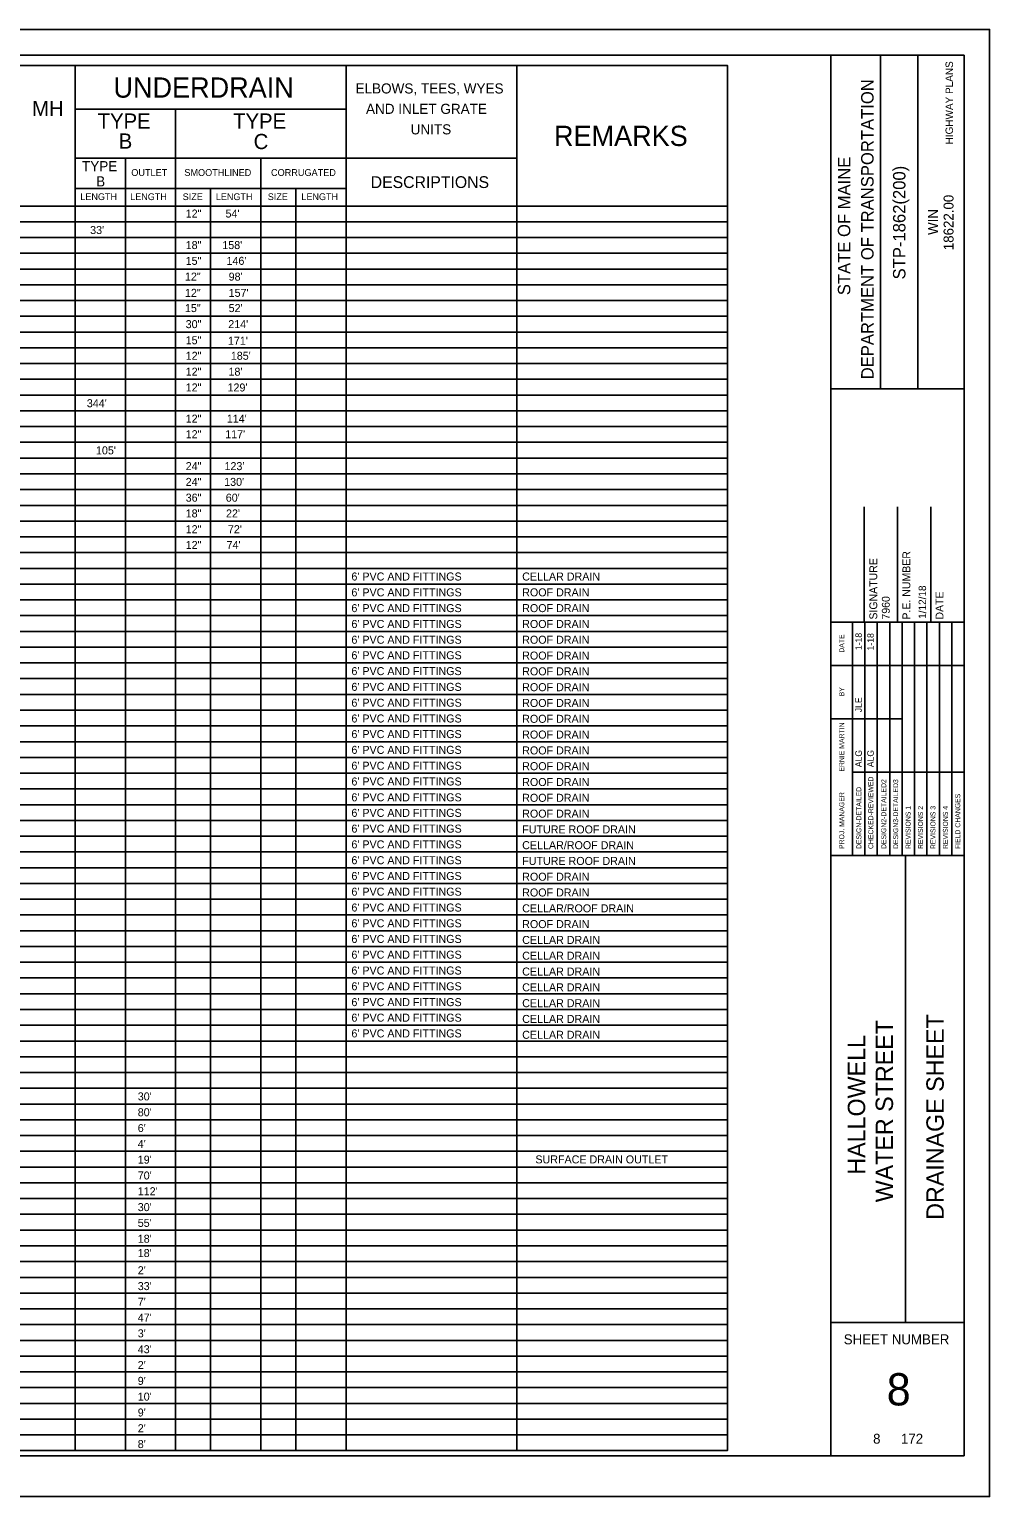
# Model space of a CAD drawing. Extents: x -0.13 to 2.7, y -0.05 to 1.78.
# Drawn here: x 1.498 to 2.698, y -0.051 to 1.782 of the extents above; entities that cross this region are included whole.
import ezdxf

# ---------------------------------------------------------------- set-up
doc = ezdxf.new("R2010")
doc.units = 0
for name, color, linetype in [('ANNOTATION', 7, 'Continuous'), ('BORDER', 7, 'Continuous'), ('PLOT BOUNDARY', 7, 'Continuous')]:
    doc.layers.add(name, color=color, linetype=linetype)

msp = doc.modelspace()

# ---------------------------------------------------------------- linework, layer by layer
at = {"layer": 'BORDER'}
for p, q in [((2.6667, 1.75), (0, 1.75)), ((2.5, 0), (2.5, 1.75)), ((2.5621, 1.3333), (2.5621, 1.75)), ((2.6087, 1.3333), (2.6087, 1.75)), ((2.6667, 0), (2.6667, 1.75)), ((1.5556, 1.6825), (1.5556, 1.7373)), ((1.8942, 1.6825), (1.8942, 1.7373)), ((2.1075, 1.6825), (2.1075, 1.7373)), ((1.5556, 1.6214), (1.5556, 1.6825)), ((1.5556, 1.6825), (1.6184, 1.6825)), ((1.6184, 1.6825), (1.7249, 1.6825)), ((1.6811, 1.6214), (1.6811, 1.6825)), ((1.7249, 1.6825), (1.7876, 1.6825)), ((1.7876, 1.6825), (1.8315, 1.6825)), ((1.8315, 1.6825), (1.8942, 1.6825)), ((1.8942, 1.6214), (1.8942, 1.6825)), ((2.1075, 1.6214), (2.1075, 1.6825)), ((1.5556, 1.5836), (1.5556, 1.6214)), ((1.5556, 1.6214), (1.6184, 1.6214)), ((1.6184, 1.5836), (1.6184, 1.6214)), ((1.6184, 1.6214), (1.7249, 1.6214)), ((1.6811, 1.5836), (1.6811, 1.6214)), ((1.7249, 1.6214), (1.8315, 1.6214)), ((1.7876, 1.5836), (1.7876, 1.6214)), ((1.8315, 1.6214), (1.8942, 1.6214)), ((1.8942, 1.5836), (1.8942, 1.6214)), ((1.8942, 1.6214), (2.1075, 1.6214)), ((2.1075, 1.5836), (2.1075, 1.6214)), ((1.5556, 1.5616), (1.5556, 1.5836)), ((1.5556, 1.5836), (1.6184, 1.5836)), ((1.6184, 1.5616), (1.6184, 1.5836)), ((1.6184, 1.5836), (1.6811, 1.5836)), ((1.6811, 1.5616), (1.6811, 1.5836)), ((1.6811, 1.5836), (1.7249, 1.5836)), ((1.7249, 1.5616), (1.7249, 1.5836)), ((1.7249, 1.5836), (1.7876, 1.5836)), ((1.7876, 1.5616), (1.7876, 1.5836)), ((1.7876, 1.5836), (1.8315, 1.5836)), ((1.8315, 1.5616), (1.8315, 1.5836)), ((1.8315, 1.5836), (1.8942, 1.5836)), ((1.8942, 1.5616), (1.8942, 1.5836)), ((2.1075, 1.5616), (2.1075, 1.5836)), ((1.5556, 1.5616), (1.5556, 0.0065)), ((1.6184, 1.5616), (1.6184, 0.0065)), ((1.6811, 1.5616), (1.6811, 0.0065)), ((1.7249, 1.5616), (1.7249, 0.0065)), ((1.7876, 1.5616), (1.7876, 0.0065)), ((1.8315, 1.5616), (1.8315, 0.0065)), ((1.8942, 1.5616), (1.8942, 0.0065)), ((2.1075, 1.5616), (2.1075, 0.0065)), ((0.1293, 1.5419), (2.3707, 1.5419)), ((0.1293, 1.5223), (2.3707, 1.5223)), ((0.1293, 1.5026), (2.3707, 1.5026)), ((0.1293, 1.4829), (2.3707, 1.4829)), ((0.1293, 1.4632), (2.3707, 1.4632)), ((0.1293, 1.4435), (2.3707, 1.4435)), ((0.1293, 1.4238), (2.3707, 1.4238)), ((0.1293, 1.4041), (2.3707, 1.4041)), ((0.1293, 1.3845), (2.3707, 1.3845)), ((0.1293, 1.3648), (2.3707, 1.3648)), ((0.1293, 1.3451), (2.3707, 1.3451)), ((0.1293, 1.3254), (2.3707, 1.3254)), ((2.5, 1.3332), (2.6667, 1.3332)), ((0.1293, 1.3057), (2.3707, 1.3057)), ((0.1293, 1.286), (2.3707, 1.286)), ((0.1293, 1.2664), (2.3707, 1.2664)), ((0.1293, 1.2467), (2.3707, 1.2467)), ((0.1293, 1.227), (2.3707, 1.227)), ((0.1293, 1.2073), (2.3707, 1.2073)), ((0.1293, 1.1876), (2.3707, 1.1876)), ((2.5417, 1.0417), (2.5417, 1.1858)), ((2.5833, 1.0417), (2.5833, 1.1858)), ((2.625, 1.0417), (2.625, 1.1858)), ((0.1293, 1.1679), (2.3707, 1.1679)), ((0.1293, 1.1482), (2.3707, 1.1482)), ((0.1293, 1.1286), (2.3707, 1.1286)), ((0.1293, 1.1089), (2.3707, 1.1089)), ((0.1293, 1.0892), (2.3707, 1.0892)), ((0.1293, 1.0695), (2.3707, 1.0695)), ((0.1293, 1.0498), (2.3707, 1.0498)), ((0.1293, 1.0301), (2.3707, 1.0301)), ((2.5, 1.0417), (2.6667, 1.0417)), ((0.1293, 1.0104), (2.3707, 1.0104)), ((0.1293, 0.9908), (2.3707, 0.9908)), ((0.1293, 0.9711), (2.3707, 0.9711)), ((0.1293, 0.9514), (2.3707, 0.9514)), ((0.1293, 0.9317), (2.3707, 0.9317)), ((0.1293, 0.912), (2.3707, 0.912)), ((0.1293, 0.8923), (2.3707, 0.8923)), ((0.1293, 0.8727), (2.3707, 0.8727)), ((0.1293, 0.853), (2.3707, 0.853)), ((0.1293, 0.8333), (2.3707, 0.8333)), ((0.1293, 0.8136), (2.3707, 0.8136)), ((0.1293, 0.7939), (2.3707, 0.7939)), ((0.1293, 0.7742), (2.3707, 0.7742)), ((0.1293, 0.7545), (2.3707, 0.7545)), ((0.1293, 0.7349), (2.3707, 0.7349)), ((2.5, 0.75), (2.6667, 0.75)), ((2.5932, 0.1667), (2.5932, 0.75)), ((0.1293, 0.7152), (2.3707, 0.7152)), ((0.1293, 0.6955), (2.3707, 0.6955)), ((0.1293, 0.6758), (2.3707, 0.6758)), ((0.1293, 0.6561), (2.3707, 0.6561)), ((0.1293, 0.6364), (2.3707, 0.6364)), ((0.1293, 0.6167), (2.3707, 0.6167)), ((0.1293, 0.5971), (2.3707, 0.5971)), ((0.1293, 0.5774), (2.3707, 0.5774)), ((0.1293, 0.5577), (2.3707, 0.5577)), ((0.1293, 0.538), (2.3707, 0.538)), ((0.1293, 0.5183), (2.3707, 0.5183)), ((0.1293, 0.4986), (2.3707, 0.4986)), ((0.1293, 0.479), (2.3707, 0.479)), ((0.1293, 0.4593), (2.3707, 0.4593)), ((0.1293, 0.4396), (2.3707, 0.4396)), ((0.1293, 0.4199), (2.3707, 0.4199)), ((0.1293, 0.4002), (2.3707, 0.4002)), ((0.1293, 0.3805), (2.3707, 0.3805)), ((0.1293, 0.3608), (2.3707, 0.3608)), ((0.1293, 0.3412), (2.3707, 0.3412)), ((0.1293, 0.3215), (2.3707, 0.3215)), ((0.1293, 0.3018), (2.3707, 0.3018)), ((0.1293, 0.2821), (2.3707, 0.2821)), ((0.1293, 0.2624), (2.3707, 0.2624)), ((0.1293, 0.2427), (2.3707, 0.2427)), ((0.1293, 0.223), (2.3707, 0.223)), ((0.1293, 0.2034), (2.3707, 0.2034)), ((0.1293, 0.1837), (2.3707, 0.1837)), ((2.5, 0.1667), (2.6667, 0.1667)), ((0.1293, 0.164), (2.3707, 0.164)), ((0.1293, 0.1443), (2.3707, 0.1443)), ((0.1293, 0.1246), (2.3707, 0.1246)), ((0.1293, 0.1049), (2.3707, 0.1049)), ((0.1293, 0.0853), (2.3707, 0.0853)), ((0.1293, 0.0656), (2.3707, 0.0656)), ((0.1293, 0.0459), (2.3707, 0.0459)), ((0.1293, 0.0262), (2.3707, 0.0262)), ((0, 0), (2.6667, 0)), ((0.1293, 0.0065), (2.3707, 0.0065))]:
    msp.add_line(p, q, dxfattribs=at)
msp.add_lwpolyline([(0.1293, 1.7373), (2.3707, 1.7373), (2.3707, 1.5616), (0.1293, 1.5616)], close=True, dxfattribs=at)
for points in [[(0.1293, 1.5616), (0.1293, 0.0065), (2.3707, 0.0065), (2.3707, 1.5616)], [(2.5269, 0.9875), (2.5269, 1.0417)], [(2.5269, 0.7501), (2.5269, 1.0299)], [(2.5425, 0.7501), (2.5425, 1.0417)], [(2.558, 1.0417), (2.558, 0.7501)], [(2.5735, 0.7501), (2.5735, 1.0417)], [(2.589, 0.7501), (2.589, 1.0417)], [(2.6046, 0.7501), (2.6046, 1.0417)], [(2.6201, 0.7501), (2.6201, 1.0417)], [(2.6356, 0.7501), (2.6356, 1.0417)], [(2.6512, 0.7501), (2.6512, 1.0417)], [(2.5, 0.9875), (2.6667, 0.9875)], [(2.5, 0.9209), (2.5269, 0.9209)], [(2.5269, 0.9209), (2.589, 0.9209)], [(2.5269, 0.8542), (2.6667, 0.8542)]]:
    msp.add_lwpolyline(points, dxfattribs=at)
at = {"layer": 'PLOT BOUNDARY'}
msp.add_lwpolyline([(-0.1349, -0.051), (2.6984, -0.051), (2.6984, 1.7823), (-0.1349, 1.7823)], close=True, dxfattribs=at)

# ---------------------------------------------------------------- texts
at = {"layer": 'ANNOTATION'}
for s, p in [('12"', (1.6938, 1.5472)), ("54'", (1.7436, 1.5472)), ("33'", (1.5744, 1.5266)), ('18"', (1.6938, 1.5078)), ("158'", (1.7396, 1.5078)), ('15"', (1.6938, 1.4881)), ("146'", (1.7448, 1.4881)), ('12"', (1.6929, 1.4684)), ("98'", (1.7475, 1.4684)), ('12"', (1.6929, 1.4481)), ("157'", (1.7475, 1.4481)), ('15"', (1.6929, 1.4291)), ("52'", (1.7475, 1.4291)), ('30"', (1.6938, 1.409)), ("214'", (1.747, 1.409)), ('15"', (1.6938, 1.3889)), ("171'", (1.7466, 1.3883)), ('12"', (1.6938, 1.3695)), ("185'", (1.7502, 1.3695)), ('12"', (1.6938, 1.3496)), ("18'", (1.7473, 1.3496)), ('12"', (1.6938, 1.3299)), ("129'", (1.7461, 1.3299)), ("344'", (1.5703, 1.3102)), ('12"', (1.6938, 1.2909)), ("114'", (1.7452, 1.2909)), ('12"', (1.6938, 1.2715)), ("117'", (1.7432, 1.2715)), ("105'", (1.5817, 1.2513)), ('24"', (1.6938, 1.2316)), ("123'", (1.7423, 1.2316)), ('24"', (1.6938, 1.2119)), ("130'", (1.7419, 1.2119)), ('36"', (1.6938, 1.1922)), ("60'", (1.7439, 1.1922)), ('18"', (1.6938, 1.1725)), ("22'", (1.7442, 1.1725)), ('12"', (1.6938, 1.1528)), ("72'", (1.7466, 1.1528)), ('12"', (1.6938, 1.1331)), ("74'", (1.7449, 1.1331)), ("6' PVC AND FITTINGS", (1.9009, 1.0937)), ('CELLAR DRAIN', (2.1143, 1.0937)), ("6' PVC AND FITTINGS", (1.9009, 1.0739)), ('ROOF DRAIN', (2.1143, 1.0739)), ("6' PVC AND FITTINGS", (1.9009, 1.0542)), ('ROOF DRAIN', (2.1143, 1.0542)), ("6' PVC AND FITTINGS", (1.9009, 1.0344)), ('ROOF DRAIN', (2.1143, 1.0344)), ("6' PVC AND FITTINGS", (1.9009, 1.0147)), ('ROOF DRAIN', (2.1143, 1.0147)), ("6' PVC AND FITTINGS", (1.9009, 0.9953)), ('ROOF DRAIN', (2.1143, 0.9949)), ("6' PVC AND FITTINGS", (1.9009, 0.9755)), ('ROOF DRAIN', (2.1143, 0.9752)), ("6' PVC AND FITTINGS", (1.9009, 0.9558)), ('ROOF DRAIN', (2.1143, 0.9554)), ("6' PVC AND FITTINGS", (1.9009, 0.936)), ('ROOF DRAIN', (2.1143, 0.9357)), ("6' PVC AND FITTINGS", (1.9009, 0.9163)), ('ROOF DRAIN', (2.1143, 0.9159)), ("6' PVC AND FITTINGS", (1.9009, 0.8968)), ('ROOF DRAIN', (2.1143, 0.8962)), ("6' PVC AND FITTINGS", (1.9009, 0.8771)), ('ROOF DRAIN', (2.1143, 0.8764)), ("6' PVC AND FITTINGS", (1.9009, 0.8573)), ('ROOF DRAIN', (2.1143, 0.8567)), ("6' PVC AND FITTINGS", (1.9009, 0.8376)), ('ROOF DRAIN', (2.1143, 0.8369)), ("6' PVC AND FITTINGS", (1.9009, 0.8178)), ('ROOF DRAIN', (2.1143, 0.8172)), ("6' PVC AND FITTINGS", (1.9009, 0.7984)), ('ROOF DRAIN', (2.1143, 0.7974)), ("6' PVC AND FITTINGS", (1.9009, 0.7787)), ('FUTURE ROOF DRAIN', (2.1143, 0.7777)), ("6' PVC AND FITTINGS", (1.9009, 0.759)), ('CELLAR/ROOF DRAIN', (2.1143, 0.758)), ("6' PVC AND FITTINGS", (1.9009, 0.7392)), ('FUTURE ROOF DRAIN', (2.1143, 0.7383)), ("6' PVC AND FITTINGS", (1.9009, 0.7195)), ('ROOF DRAIN', (2.1143, 0.7186)), ("6' PVC AND FITTINGS", (1.9009, 0.6999)), ('ROOF DRAIN', (2.1143, 0.6989)), ("6' PVC AND FITTINGS", (1.9009, 0.6801)), ('CELLAR/ROOF DRAIN', (2.1143, 0.6791)), ("6' PVC AND FITTINGS", (1.9009, 0.6604)), ('ROOF DRAIN', (2.1143, 0.6594)), ("6' PVC AND FITTINGS", (1.9009, 0.6409)), ('CELLAR DRAIN', (2.1143, 0.6396)), ("6' PVC AND FITTINGS", (1.9009, 0.6212)), ('CELLAR DRAIN', (2.1143, 0.6199)), ("6' PVC AND FITTINGS", (1.9009, 0.6014)), ('CELLAR DRAIN', (2.1143, 0.6001)), ("6' PVC AND FITTINGS", (1.9009, 0.5817)), ('CELLAR DRAIN', (2.1143, 0.5804)), ("6' PVC AND FITTINGS", (1.9009, 0.5619)), ('CELLAR DRAIN', (2.1143, 0.5606)), ("6' PVC AND FITTINGS", (1.9009, 0.5425)), ('CELLAR DRAIN', (2.1143, 0.5409)), ("6' PVC AND FITTINGS", (1.9009, 0.5228)), ('CELLAR DRAIN', (2.1143, 0.5211)), ("30'", (1.6339, 0.4441)), ("80'", (1.6339, 0.4243)), ("6'", (1.6339, 0.4046)), ("4'", (1.6339, 0.3848)), ("19'", (1.6339, 0.3651)), ('SURFACE DRAIN OUTLET', (2.1308, 0.3654)), ("70'", (1.6339, 0.3453)), ("112'", (1.6339, 0.3256)), ("30'", (1.6339, 0.3058)), ("55'", (1.6339, 0.2861)), ("18'", (1.6339, 0.2663)), ("18'", (1.6339, 0.2484)), ("2'", (1.6339, 0.2269)), ("33'", (1.6339, 0.2071)), ("7'", (1.6339, 0.1875)), ("47'", (1.6339, 0.1677)), ("3'", (1.6339, 0.148)), ("43'", (1.6339, 0.1282)), ("2'", (1.6339, 0.1085)), ("9'", (1.6339, 0.0887)), ("10'", (1.6339, 0.069)), ("9'", (1.6339, 0.0492)), ("2'", (1.6339, 0.0295)), ("8'", (1.6339, 0.0097))]:
    msp.add_text(s, height=0.01, dxfattribs=at).set_placement(p)
at = {"layer": 'BORDER'}
for s, height, p in [('HIGHWAY PLANS', 0.009317, (2.6526, 1.6386)), ('DEPARTMENT OF TRANSPORTATION', 0.015529, (2.5534, 1.3451)), ('STATE OF MAINE', 0.015529, (2.5243, 1.4502)), ('STP-1862(200)', 0.015529, (2.5932, 1.4699)), ('18622.00', 0.01242, (2.6533, 1.5064)), ('WIN', 0.01242, (2.6339, 1.5255)), ('SIGNATURE', 0.00984, (2.558, 1.0449)), ('P.E. NUMBER', 0.009843, (2.5993, 1.0449)), ('1/12/18', 0.00935, (2.619, 1.0458)), ('7960', 0.00984, (2.5736, 1.0449)), ('DATE', 0.00984, (2.6407, 1.0449)), ('1-18', 0.00808, (2.5387, 1.0067)), ('1-18', 0.00808, (2.5536, 1.0063)), ('DATE', 0.00619, (2.5167, 1.0035)), ('BY', 0.00619, (2.5167, 0.949)), ('JLE', 0.00808, (2.5387, 0.929)), ('ERNIE MARTIN', 0.006212, (2.5167, 0.8549)), ('ALG', 0.00808, (2.5387, 0.8604)), ('ALG', 0.00808, (2.5536, 0.8604)), ('CHECKED-REVIEWED', 0.006212, (2.553, 0.7582)), ('PROJ. MANAGER', 0.006212, (2.5167, 0.7582)), ('DESIGN-DETAILED', 0.006212, (2.5381, 0.7582)), ('DESIGN2-DETAILED2', 0.006212, (2.5692, 0.7582)), ('DESIGN3-DETAILED3', 0.006212, (2.5841, 0.7582)), ('REVISIONS 1', 0.006212, (2.5996, 0.7582)), ('REVISIONS 2', 0.006212, (2.6151, 0.7582)), ('REVISIONS 3', 0.006212, (2.6307, 0.7582)), ('REVISIONS 4', 0.006212, (2.6462, 0.7582)), ('FIELD CHANGES', 0.006212, (2.6617, 0.7582)), ('DRAINAGE SHEET', 0.021738, (2.6411, 0.2949)), ('WATER STREET', 0.021738, (2.5777, 0.3168)), ('HALLOWELL', 0.02174, (2.5429, 0.3513))]:
    msp.add_text(s, height=height, rotation=90, dxfattribs=at).set_placement(p)
for s, height, p in [('UNDERDRAIN', 0.02528, (1.6035, 1.697)), ('ELBOWS, TEES, WYES', 0.012638, (1.906, 1.7022)), ('MH', 0.01896, (1.5018, 1.674)), ('AND INLET GRATE', 0.012638, (1.9191, 1.6767)), ('TYPE', 0.01896, (1.5838, 1.6583)), ('TYPE', 0.01896, (1.7531, 1.6583)), ('B', 0.019, (1.6101, 1.6333)), ('C', 0.019, (1.7787, 1.6327)), ('UNITS', 0.01264, (1.9749, 1.6511)), ('REMARKS', 0.02528, (2.154, 1.6366)), ('TYPE', 0.01264, (1.5642, 1.6051)), ('B', 0.0126, (1.5819, 1.5861)), ('OUTLET', 0.00853, (1.6258, 1.5992)), ('SMOOTHLINED', 0.008531, (1.6921, 1.5992)), ('CORRUGATED', 0.00853, (1.8004, 1.5992)), ('DESCRIPTIONS', 0.014744, (1.925, 1.5841)), ('LENGTH', 0.00843, (1.5622, 1.569)), ('LENGTH', 0.00843, (1.6245, 1.569)), ('SIZE', 0.00843, (1.6901, 1.569)), ('LENGTH', 0.00843, (1.7315, 1.569)), ('SIZE', 0.00843, (1.7964, 1.569)), ('LENGTH', 0.00843, (1.8384, 1.569)), ('SHEET NUMBER', 0.012421, (2.5161, 0.1394)), ('8', 0.0403, (2.5698, 0.063)), ('8', 0.0124, (2.5528, 0.0152)), ('172', 0.01242, (2.5876, 0.0152))]:
    msp.add_text(s, height=height, dxfattribs=at).set_placement(p)

doc.saveas('drawing.dxf')
